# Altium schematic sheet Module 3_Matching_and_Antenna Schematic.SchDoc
size A4; DocumentNumber: 5; SheetNumber: 5; SheetTotal: 5; PageSetup: Record=PageOptions¦CenterHorizontal=True¦CenterVertical=True¦PrintScale=0.97¦XCorrection=1.00¦YCorrection=1.00¦PrintKind=0¦BorderSize=5000000¦LeftOffset=0¦BottomOffset=0¦Orientation=2¦PaperLength=1000¦PaperWidth=1000¦Scale=100¦PaperSource=7¦PrintQuality=-4¦MediaType=1¦DitherType=10¦PaperKind=A4¦PrintScaleMode=1
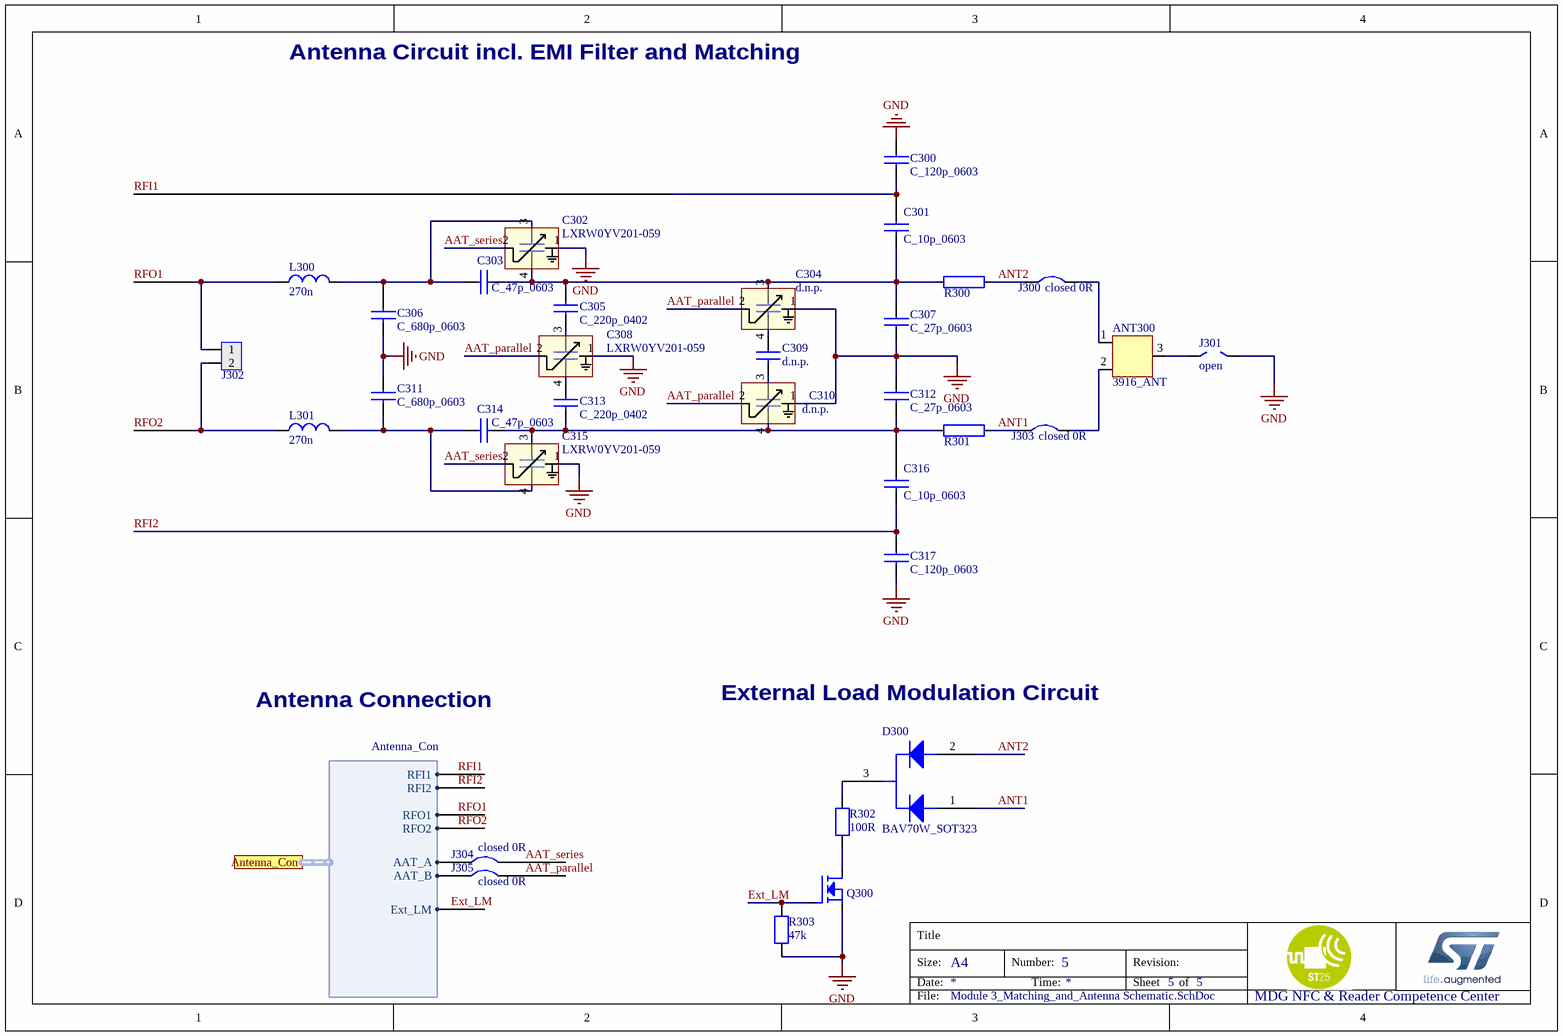
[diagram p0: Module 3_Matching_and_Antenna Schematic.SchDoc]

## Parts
ANT300  3916_ANT  [ST25R_3916DB__ANTL_66x66mm]  (net tie, no BOM)
C300  C_120p_0603  [C0603]
C301  C_10p_0603  [C0603]
C302  LXRW0YV201-059  [Vcap_csp_combo]
C303  C_47p_0603  [C0603]
C304  d.n.p.  [Vcap_csp_combo]
C305  C_220p_0402  [C0402]
C306  C_680p_0603  [C0603]
C307  C_27p_0603  [C0603]
C308  LXRW0YV201-059  [Vcap_csp_combo]
C309  d.n.p.  [C0402]
C310  d.n.p.  [Vcap_csp_combo]
C311  C_680p_0603  [C0603]
C312  C_27p_0603  [C0603]
C313  C_220p_0402  [C0402]
C314  C_47p_0603  [C0603]
C315  LXRW0YV201-059  [Vcap_csp_combo]
C316  C_10p_0603  [C0603]
C317  C_120p_0603  [C0603]
D300  BAV70W_SOT323  [SOT323]
J300  closed 0R  [JP2_SMD_closed_0402]
J301  open  [JP2_SMD_open_0402]  (no BOM)
J302  d.n.p.  [HDR1X2_slim]  (value not drawn)  (no BOM)
J303  closed 0R  [JP2_SMD_closed_0402]
J304  closed 0R  [JP2_SMD_closed_0402]
J305  closed 0R  [JP2_SMD_closed_0402]
L300  270n  [L0603]
L301  270n  [L0603]
Q300  NX3008NBK  [SOT23]  (value not drawn)
R300  2R2  [R0603]  (value not drawn)
R301  2R2  [R0603]  (value not drawn)
R302  100R  [R0402]
R303  47k  [R0402]

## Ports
Antenna_Con (harness Antenna_Con)

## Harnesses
Antenna_Con: RFI1, RFI2, RFO1, RFO2, AAT_A, AAT_B, Ext_LM

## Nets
GND: C300.1 C302.1 C304.1 C306.2 C307.2 C308.1 C310.1 C311.1 C312.1 C315.1 C317.2 J301.2 Q300.2(S) R303.1
AAT_parallel: C304.2 C308.2 C310.2 J305.2
AAT_series: C302.2 C315.2 J304.2
ANT1: D300.1(A1) J303.1 R301.1
ANT2: D300.2(A2) J300.1 R300.1
Ext_LM: Q300.1(G) R303.2 ; port Antenna_Con.Ext_LM
RFI1: C300.2 C301.1 ; port Antenna_Con.RFI1
RFI2: C316.2 C317.1 ; port Antenna_Con.RFI2
RFO1: J302.1 L300.2 ; port Antenna_Con.RFO1
RFO2: J302.2 L301.2 ; port Antenna_Con.RFO2
NetANT300_1: ANT300.1 J300.2
NetANT300_2: ANT300.2 J303.2
NetANT300_3: ANT300.3 J301.1
NetC301_2: C301.2 C302.4 C303.2 C304.3 C305.1 C307.1 R300.2
NetC302_3: C302.3 C303.1 C306.1 L300.1
NetC304_4: C304.4 C309.1
NetC305_2: C305.2 C308.3
NetC308_4: C308.4 C313.1
NetC309_2: C309.2 C310.3
NetC310_4: C310.4 C312.2 C313.2 C314.2 C315.3 C316.1 R301.2
NetC311_2: C311.2 C314.1 C315.4 L301.1
NetD300_3: D300.3(K) R302.2
NetJ304_1: J304.1 ; port Antenna_Con.AAT_A
NetJ305_1: J305.1 ; port Antenna_Con.AAT_B
NetQ300_3: Q300.3(D) R302.1

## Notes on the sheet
- Antenna Circuit incl. EMI Filter and Matching
- Antenna Connection
- (near D300) External Load Modulation Circuit

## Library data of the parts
ANT300 = 3916_ANT: ST25R3916 DB Ant
C300 C317 = C_120p_0603: 120p_COG; Manufacturer: MURATA; Manufacturer Part Number: GRM1885C1H121GA01D; 2nd Source: 120pF ±2% 50V  C0G, NP0 0603
C301 C316 = C_10p_0603: 10p_COG; Manufacturer: MULTICOMP; Manufacturer Part Number: MC0603N100F500CT; 2nd Source: 0603, 10pF, 50 V, 1%, C0G / NP0
C302 C308 C315 = Vcap: Manufacturer: muRata
C303 C314 = C_47p_0603: 47p_COG; Manufacturer: MURATA; Manufacturer Part Number: GRM1885C1H470FA01D; 2nd Source: 47pF ±2% 50V  C0G, NP0 0603
C304 C310 = Vcap: Manufacturer: muRata; Manufacturer Part Number: LXRW0YV201-059
C305 C309 C313 = C_220p_0402: 220p_COG; Manufacturer: MURATA; Manufacturer Part Number: GRM1885C1H221FA01D; 2nd Source: 220pF ±2% 50V  C0G, NP0 0402
C306 C311 = C_680p_0603: 680p_COG; Manufacturer: MURATA; Manufacturer Part Number: GRM1885C1H681GA01D; 2nd Source: 680pF ±2% 50V  C0G, NP0 0603
C307 C312 = C_27p_0603: 27p_COG; Manufacturer: MURATA; Manufacturer Part Number: GRM1885C1H270FA01D; 2nd Source: 27pF ±2% 50V  C0G, NP0 0603
D300 = 1PS70SB85_SOT323
J300 J303-J305 = solder_jumper_closed_0402: 0R; Manufacturer: Multicomp; Manufacturer Part Number: MC00625W040210R
J301 = solder_jumper_open_0402
J302 = Header 2: Male Single Row Horizontal 2 pin; 2nd Source: doublesourcing allowed
L300 L301 = 0603LS-241XJLB: MLJ1608WR27JT000; Manufacturer: TDK; 2nd Source: 0.27 uH 5 % 0.55A 0603
Q300 = NX3008NBK: nCh MOS Fet - NX3008NBK
R300 R301 = R0603_2R2: 2R2, 0603; Manufacturer: Vishay Dale; Manufacturer Part Number: CRCW06032R20FKEA; 2nd Source: 2.2 Ohm ±1% 0.1W, 1/10W Chip Resistor 0603
R302 = R_0603: 2nd Source: 100R 0402
R303 = R_0603: 2nd Source: 47k 0402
